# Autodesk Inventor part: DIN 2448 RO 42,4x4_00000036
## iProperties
Created: 2006-02
Part Number: DIN 2448 RO 42,4x4_00000036
Material: Default
Document SubType Name: Modeling
Designer: FranzK
Stock Number: DIN 2448 RO 42,4x4
Mass: 332.959 g
Surface Area: 1674.44 cm^2
Volume: 332.959 cm^3
Density: 1 g/cm^3
G_L: 690.000 mm
G_W: 42.400 mm
G_H: 42.400 mm
AFG_Item: 42.4 x 4
CSToolsMass: 0.3
CSToolsVolume: 332959.0
CSToolsArea: 1674.0
Author: FranzK
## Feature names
1. AFG_Detailed_DIN 2448 RO 42,4x4_00000036 [Extrusion]
2. AFG_Simplified_DIN 2448 RO 42,4x4_00000036 [Extrusion]
